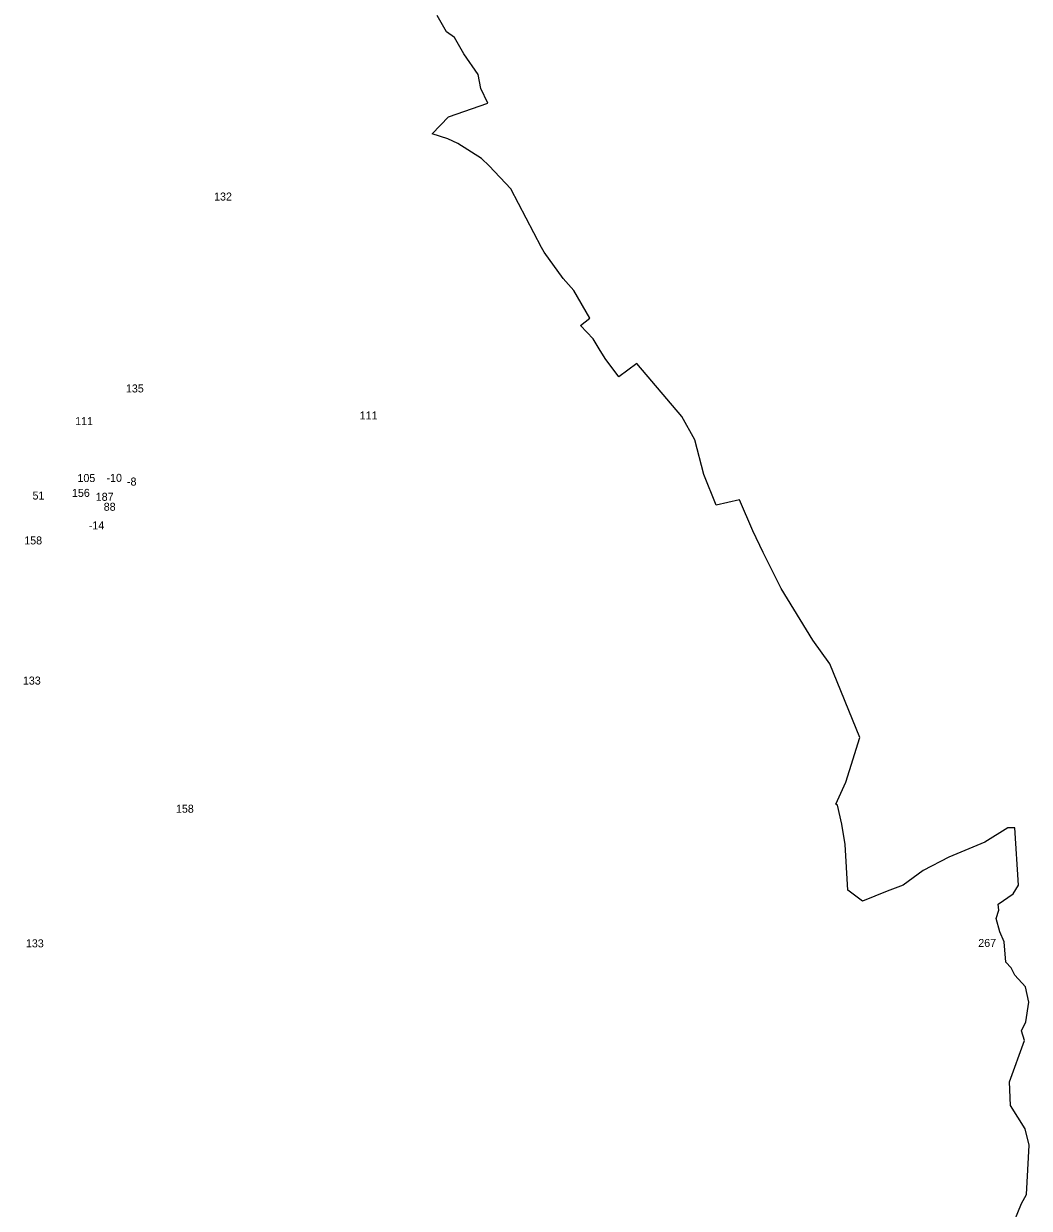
# Model space of a CAD drawing. Extents: x -787692 to -782531, y -972586 to -966265.
# Drawn here: x -783788 to -782531, y -970904 to -969423 of the extents above; entities that cross this region are included whole.
import ezdxf

# ---------------------------------------------------------------- set-up
doc = ezdxf.new("R2010")
doc.units = 0
for name, color, linetype in [('Vrstva 13', 7, 'Continuous'), ('Vrstva 15', 7, 'Continuous'), ('Vrstva 24', 7, 'Continuous')]:
    doc.layers.add(name, color=color, linetype=linetype)

msp = doc.modelspace()

# ---------------------------------------------------------------- linework, layer by layer
at = {"layer": 'Vrstva 13'}
for p, q in [((-783258.93, -969433.08), (-783270.68, -969412.96)), ((-783249.14, -969440.28), (-783258.93, -969433.08)), ((-783237.33, -969460.76), (-783249.14, -969440.28)), ((-783219.6, -969486.34), (-783237.33, -969460.76)), ((-783216.12, -969503.99), (-783219.6, -969486.34)), ((-783207.54, -969522.48), (-783216.12, -969503.99)), ((-783256.74, -969539.31), (-783207.54, -969522.48)), ((-783276.8, -969560.88), (-783256.74, -969539.31)), ((-783257.3, -969566.96), (-783276.8, -969560.88)), ((-783244.76, -969572.78), (-783257.3, -969566.96)), ((-783215.47, -969591.64), (-783244.76, -969572.78)), ((-783205.92, -969600.87), (-783215.47, -969591.64)), ((-783178.66, -969629.28), (-783205.92, -969600.87)), ((-783140.31, -969702.61), (-783178.66, -969629.28)), ((-783136.99, -969708.6), (-783140.31, -969702.61)), ((-783113.37, -969741.38), (-783136.99, -969708.6)), ((-783100.1, -969756.36), (-783113.37, -969741.38)), ((-783079.88, -969790.93), (-783100.1, -969756.36)), ((-783091.45, -969800.31), (-783079.88, -969790.93)), ((-783075.67, -969817.07), (-783091.45, -969800.31)), ((-783068.31, -969829.29), (-783075.67, -969817.07)), ((-783060.7, -969841.51), (-783068.31, -969829.29)), ((-783043.63, -969864.42), (-783060.7, -969841.51)), ((-783021.3, -969847.82), (-783043.63, -969864.42)), ((-782964.83, -969914.11), (-783021.3, -969847.82)), ((-782948.65, -969943.13), (-782964.83, -969914.11)), ((-782937.56, -969986.47), (-782948.65, -969943.13)), ((-782921.87, -970024.8), (-782937.56, -969986.47)), ((-782892.99, -970018.21), (-782921.87, -970024.8)), ((-782876.07, -970056.7), (-782892.99, -970018.21)), ((-782863.45, -970083.89), (-782876.07, -970056.7)), ((-782840.64, -970128.89), (-782863.45, -970083.89)), ((-782801.24, -970193.6), (-782840.64, -970128.89)), ((-782780.12, -970223.14), (-782801.24, -970193.6)), ((-782742.43, -970315.26), (-782780.12, -970223.14)), ((-782755.22, -970356.46), (-782742.43, -970315.26)), ((-782759.9, -970371.1), (-782755.22, -970356.46)), ((-782772.28, -970398.46), (-782759.9, -970371.1)), ((-782770.51, -970399.67), (-782772.28, -970398.46)), ((-782764.93, -970423.59), (-782770.51, -970399.67)), ((-782760.72, -970449), (-782764.93, -970423.59)), ((-782557.66, -970428.12), (-782586.14, -970446.17)), ((-782548.61, -970428.07), (-782557.66, -970428.12)), ((-782544.24, -970499.79), (-782548.61, -970428.07)), ((-782757.57, -970506.02), (-782760.72, -970449)), ((-782586.14, -970446.17), (-782631.04, -970464.71)), ((-782631.04, -970464.71), (-782663.48, -970481.62)), ((-782663.48, -970481.62), (-782688.4, -970499.71)), ((-782688.4, -970499.71), (-782708.14, -970507.16)), ((-782550.64, -970510.72), (-782544.24, -970499.79)), ((-782739.21, -970519.86), (-782757.57, -970506.02)), ((-782708.14, -970507.16), (-782739.21, -970519.86)), ((-782569.69, -970523.46), (-782550.64, -970510.72)), ((-782571.87, -970541.43), (-782568.64, -970531.15)), ((-782568.64, -970531.15), (-782569.69, -970523.46)), ((-782567.46, -970558.28), (-782571.87, -970541.43)), ((-782562.12, -970570.58), (-782567.46, -970558.28)), ((-782560.09, -970595.99), (-782562.12, -970570.58)), ((-782553.3, -970603.28), (-782560.09, -970595.99)), ((-782548.73, -970612.41), (-782553.3, -970603.28)), ((-782535.59, -970626.87), (-782548.73, -970612.41)), ((-782531.3, -970646.21), (-782535.59, -970626.87)), ((-782534.82, -970670.68), (-782531.3, -970646.21)), ((-782540.44, -970681.89), (-782534.82, -970670.68)), ((-782555.52, -970745.67), (-782536.6, -970693.83)), ((-782536.6, -970693.83), (-782540.44, -970681.89)), ((-782554.1, -970775.11), (-782555.52, -970745.67)), ((-782535.74, -970804.32), (-782554.1, -970775.11)), ((-782530.65, -970824.72), (-782535.74, -970804.32)), ((-782534.2, -970886.31), (-782530.65, -970824.72)), ((-782540.43, -970897.48), (-782534.2, -970886.31)), ((-782553.45, -970929.37), (-782540.43, -970897.48))]:
    msp.add_line(p, q, dxfattribs=at)

# ---------------------------------------------------------------- texts
at = {"layer": 'Vrstva 15'}
for s, p in [('135', (-783659.791, -969883.92)), ('111', (-783367.62, -969917.7)), ('111', (-783723.22, -969924.74)), ('-10', (-783684.065, -969995.66)), ('-8', (-783658.47, -970000.31)), ('51', (-783776.521, -970017.76)), ('156', (-783727.214, -970014.47)), ('88', (-783687.516, -970031.79)), ('-14', (-783706.21, -970055.08))]:
    msp.add_text(s, height=10, dxfattribs=at).set_placement(p)
at = {"layer": 'Vrstva 24'}
for s, p in [('132', (-783549.581, -969644.04)), ('105', (-783720.35, -969995.89)), ('187', (-783697.5, -970019.38)), ('158', (-783786.851, -970073.9)), ('133', (-783788.561, -970249.05)), ('158', (-783597.261, -970409.23)), ('133', (-783784.781, -970577.51)), ('267', (-782594.458, -970576.99))]:
    msp.add_text(s, height=10, dxfattribs=at).set_placement(p)

doc.saveas('drawing.dxf')
